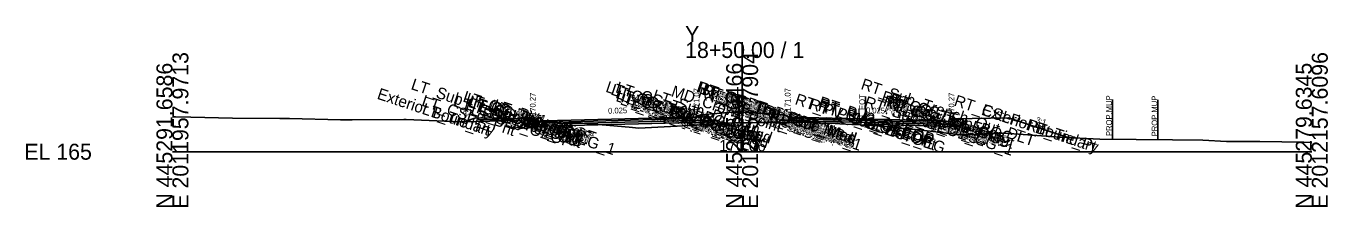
# Model space of a CAD drawing. Extents: x -26 to 3203, y -10 to 9532.
# Drawn here: x 974.3 to 1202.8, y 2490.3 to 2522.1 of the extents above; entities that cross this region are included whole.
import ezdxf

# ---------------------------------------------------------------- set-up
doc = ezdxf.new("R2010")
doc.units = 0
for name, color, linetype in [('Default', 7, 'Continuous'), ('Exist CMT Pavement', 7, 'Continuous'), ('Exist Cross Section Cell', 7, 'Continuous'), ('Exist XS Center Line Elevation Label', 7, 'Continuous'), ('Exist XS Ground Line', 7, 'Continuous'), ('Prop CMT Conc Surface', 7, 'Continuous'), ('Prop CMT Concrete Structures', 7, 'Continuous'), ('Prop CMT Pvmt Course 1', 7, 'Continuous'), ('Prop CMT Pvmt Course 1 CG', 7, 'Continuous'), ('Prop CMT Pvmt Course 2', 7, 'Continuous'), ('Prop CMT Pvmt Course 2 Wedge', 7, 'Continuous'), ('Prop CMT Pvmt Course 3', 7, 'Continuous'), ('Prop CMT Pvmt Course 3 Wedge', 7, 'Continuous'), ('Prop CMT Pvmt Surface', 7, 'Continuous'), ('Prop CMT Slope Grass', 7, 'Continuous'), ('Prop CMT Subgrade Earthwork', 7, 'Continuous'), ('Prop XS Hydro Elevations', 7, 'Continuous'), ('Prop XS Label Text', 7, 'Continuous'), ('Prop XS SE Text', 7, 'Continuous'), ('Prop XS Side Slope Text', 7, 'Continuous'), ('Scratch_Level_0', 7, 'Continuous')]:
    doc.layers.add(name, color=color, linetype=linetype)

msp = doc.modelspace()

# ---------------------------------------------------------------- linework, layer by layer
at = {"layer": 'Exist CMT Pavement'}
msp.add_lwpolyline([(1108.75, 2505.14), (1109.21, 2505.14), (1109.24, 2505.14), (1109.27, 2505.14), (1110.8, 2505.17), (1111.66, 2505.15), (1111.75, 2505.15), (1111.87, 2505.14), (1114.24, 2505.03), (1116.34, 2504.95), (1116.74, 2504.94), (1117.18, 2504.91), (1119.25, 2504.79), (1119.8, 2504.76), (1121.66, 2504.67), (1121.72, 2504.67), (1121.75, 2504.66), (1122.65, 2504.62), (1123.1, 2504.6), (1123.77, 2504.56)], dxfattribs=at)
at = {"layer": 'Exist Cross Section Cell'}
for p, q in [((1100, 2500), (1100, 2519.25)), ((1000, 2500), (1100, 2500)), ((1100, 2500), (1200, 2500))]:
    msp.add_line(p, q, dxfattribs=at)
at = {"layer": 'Exist XS Ground Line'}
msp.add_lwpolyline([(1000, 2506.15), (1000.53, 2506.15), (1003.22, 2506.08), (1010.55, 2505.87), (1018.83, 2505.82), (1020.57, 2505.8), (1029.49, 2505.6), (1030.59, 2505.61), (1031.57, 2505.59), (1040.61, 2505.63), (1041.02, 2505.63), (1047.77, 2505.37), (1050.81, 2505.25), (1060.65, 2505.45), (1061.47, 2505.43), (1070.67, 2505.13), (1080.19, 2504.28), (1081.89, 2504.12), (1088.55, 2504.51), (1098.48, 2505.04), (1098.93, 2505.05), (1099.5, 2505.06), (1100, 2505.06), (1101.09, 2505.06), (1101.74, 2505.07), (1103.9, 2505.1), (1104.25, 2505.11), (1104.56, 2505.11), (1106.76, 2505.12), (1109.27, 2505.14), (1110.8, 2505.17), (1111.87, 2505.14), (1114.24, 2505.03), (1116.34, 2504.95), (1116.74, 2504.94), (1117.18, 2504.91), (1119.25, 2504.79), (1119.8, 2504.76), (1121.66, 2504.67), (1122.65, 2504.62), (1123.1, 2504.6), (1123.77, 2504.56), (1131.01, 2503.86), (1138.47, 2502.96), (1146.09, 2503.28), (1155.86, 2502.55), (1162.82, 2502.2), (1175.55, 2502.11), (1180.88, 2502.03), (1185.01, 2501.82), (1190.9, 2501.78), (1198.59, 2501.65), (1200, 2501.64)], dxfattribs=at)
at = {"layer": 'Prop CMT Conc Surface'}
for points in [[(1058.75, 2505.86), (1053.75, 2505.96)], [(1063.25, 2505.27), (1063.25, 2505.77), (1062.75, 2505.77)], [(1065.25, 2505.4), (1063.25, 2505.27)], [(1091.25, 2506.05), (1092, 2506.07), (1092, 2506.24), (1092.76, 2506.49)], [(1108.75, 2506.05), (1108, 2506.07), (1108, 2506.24), (1107.24, 2506.49)], [(1134.75, 2505.4), (1136.75, 2505.27)], [(1136.75, 2505.27), (1136.75, 2505.77), (1137.25, 2505.77)]]:
    msp.add_lwpolyline(points, dxfattribs=at)
at = {"layer": 'Prop CMT Concrete Structures'}
for points in [[(1053.75, 2505.63), (1053.75, 2505.96)], [(1053.75, 2505.96), (1058.75, 2505.86)], [(1058.75, 2505.53), (1053.75, 2505.63)], [(1058.75, 2505.86), (1058.75, 2505.53)], [(1065.25, 2505.4), (1063.25, 2505.27), (1063.25, 2505.77), (1062.75, 2505.77)], [(1062.75, 2505.77), (1062.75, 2504.76), (1065.25, 2504.82)], [(1065.25, 2504.82), (1065.25, 2505.4)], [(1091.25, 2506.05), (1092, 2506.07), (1092, 2506.24), (1092.76, 2506.49)], [(1091.25, 2505.47), (1091.25, 2506.05)], [(1092.76, 2505.51), (1091.25, 2505.47)], [(1092.76, 2506.49), (1092.76, 2505.51)], [(1108.75, 2506.05), (1108, 2506.07), (1108, 2506.24), (1107.24, 2506.49)], [(1107.24, 2506.49), (1107.24, 2505.51)], [(1107.24, 2505.51), (1108.75, 2505.47)], [(1108.75, 2505.47), (1108.75, 2506.05)], [(1134.75, 2505.4), (1136.75, 2505.27), (1136.75, 2505.77), (1137.25, 2505.77)], [(1137.25, 2505.77), (1137.25, 2504.76), (1134.75, 2504.82)], [(1134.75, 2504.82), (1134.75, 2505.4)]]:
    msp.add_lwpolyline(points, dxfattribs=at)
at = {"layer": 'Prop CMT Pvmt Course 1'}
for points in [[(1091.25, 2506.05), (1065.25, 2505.4)], [(1065.25, 2505.15), (1091.25, 2505.8)], [(1065.25, 2505.4), (1065.25, 2505.15)], [(1091.25, 2505.8), (1091.25, 2506.05)], [(1091.25, 2505.8), (1091.25, 2505.8), (1091.25, 2505.8)], [(1108.75, 2506.05), (1134.75, 2505.4)], [(1108.75, 2505.8), (1108.75, 2506.05)], [(1134.75, 2505.15), (1123.77, 2505.43), (1108.75, 2505.8)], [(1108.75, 2505.8), (1108.75, 2505.8)], [(1134.75, 2505.4), (1134.75, 2505.15)]]:
    msp.add_lwpolyline(points, dxfattribs=at)
at = {"layer": 'Prop CMT Pvmt Course 1 CG'}
for points in [[(1065.25, 2504.82), (1062.25, 2504.74), (1061.91, 2504.4)], [(1065.25, 2504.49), (1065.25, 2504.82)], [(1091.25, 2505.47), (1093.26, 2505.52), (1093.59, 2505.19)], [(1091.25, 2505.14), (1091.25, 2505.47)], [(1093.59, 2505.19), (1091.25, 2505.14)], [(1108.75, 2505.47), (1106.74, 2505.52), (1106.41, 2505.19)], [(1106.41, 2505.19), (1108.75, 2505.14)], [(1108.75, 2505.14), (1108.75, 2505.47)], [(1134.75, 2504.82), (1137.75, 2504.74), (1138.09, 2504.4)], [(1134.75, 2504.49), (1134.75, 2504.82)], [(1061.91, 2504.4), (1065.25, 2504.49)], [(1138.09, 2504.4), (1134.75, 2504.49)]]:
    msp.add_lwpolyline(points, dxfattribs=at)
at = {"layer": 'Prop CMT Pvmt Course 2'}
for points in [[(1091.25, 2505.8), (1065.25, 2505.15)], [(1065.25, 2504.82), (1091.25, 2505.47)], [(1065.25, 2505.15), (1065.25, 2504.82)], [(1091.25, 2505.47), (1091.25, 2505.8)], [(1108.75, 2505.8), (1108.75, 2505.8)], [(1121.66, 2505.15), (1121.66, 2505.48)], [(1121.66, 2505.48), (1134.75, 2505.15)], [(1134.75, 2504.82), (1121.66, 2505.15)], [(1134.75, 2505.15), (1134.75, 2504.82)]]:
    msp.add_lwpolyline(points, dxfattribs=at)
msp.add_lwpolyline([(1108.75, 2505.8), (1108.75, 2505.47), (1108.75, 2505.47)], close=True, dxfattribs=at)
at = {"layer": 'Prop CMT Pvmt Course 2 Wedge'}
for points in [[(1108.75, 2505.47), (1108.75, 2505.8)], [(1108.75, 2505.8), (1109.21, 2505.79), (1109.24, 2505.79), (1109.27, 2505.79), (1110.8, 2505.75), (1111.66, 2505.73), (1111.75, 2505.73), (1111.87, 2505.72), (1114.24, 2505.66), (1116.34, 2505.61), (1116.74, 2505.6), (1117.18, 2505.59), (1119.25, 2505.54), (1119.8, 2505.53), (1121.66, 2505.48)], [(1121.66, 2505.15), (1119.8, 2505.19), (1119.25, 2505.21), (1117.18, 2505.26), (1116.74, 2505.27), (1116.34, 2505.28), (1114.24, 2505.33), (1111.87, 2505.39), (1111.75, 2505.39), (1111.66, 2505.4), (1110.8, 2505.42), (1109.27, 2505.46), (1109.24, 2505.46), (1109.21, 2505.46), (1108.75, 2505.47)], [(1121.66, 2505.48), (1121.66, 2505.15), (1121.66, 2505.15)]]:
    msp.add_lwpolyline(points, dxfattribs=at)
at = {"layer": 'Prop CMT Pvmt Course 3'}
for points in [[(1091.25, 2505.47), (1065.25, 2504.82)], [(1065.25, 2504.49), (1091.25, 2505.14)], [(1065.25, 2504.82), (1065.25, 2504.49)], [(1091.25, 2505.14), (1091.25, 2505.47)], [(1108.75, 2505.47), (1108.75, 2505.47), (1108.75, 2505.14), (1108.75, 2505.14)], [(1108.75, 2505.14), (1108.75, 2505.47)], [(1121.66, 2505.15), (1134.75, 2504.82)], [(1121.66, 2504.81), (1121.66, 2505.15)], [(1134.75, 2504.49), (1121.66, 2504.81)], [(1134.75, 2504.82), (1134.75, 2504.49)]]:
    msp.add_lwpolyline(points, dxfattribs=at)
at = {"layer": 'Prop CMT Pvmt Course 3 Wedge'}
for points in [[(1108.75, 2505.14), (1108.75, 2505.47)], [(1108.75, 2505.47), (1109.21, 2505.46), (1109.24, 2505.46), (1109.27, 2505.46), (1110.8, 2505.42), (1111.66, 2505.4), (1111.75, 2505.39), (1111.87, 2505.39), (1114.24, 2505.33), (1116.34, 2505.28), (1116.74, 2505.27), (1117.18, 2505.26), (1119.25, 2505.21), (1119.8, 2505.19), (1121.66, 2505.15)], [(1123.77, 2504.56), (1123.1, 2504.6), (1122.65, 2504.62), (1121.75, 2504.66), (1121.72, 2504.67), (1121.66, 2504.67), (1119.8, 2504.76), (1119.25, 2504.79), (1117.18, 2504.91), (1116.74, 2504.94), (1116.34, 2504.95), (1114.24, 2505.03), (1111.87, 2505.14), (1111.75, 2505.15), (1111.66, 2505.15), (1110.8, 2505.17), (1109.27, 2505.14), (1109.24, 2505.14), (1109.21, 2505.14), (1108.75, 2505.14)], [(1121.66, 2505.15), (1121.66, 2504.67)]]:
    msp.add_lwpolyline(points, dxfattribs=at)
at = {"layer": 'Prop CMT Pvmt Surface'}
for points in [[(1091.25, 2506.05), (1065.25, 2505.4)], [(1108.75, 2506.05), (1134.75, 2505.4)]]:
    msp.add_lwpolyline(points, dxfattribs=at)
at = {"layer": 'Prop CMT Slope Grass'}
for points in [[(1053.25, 2505.96), (1051.15, 2505.26)], [(1062.75, 2505.77), (1053.25, 2505.96)], [(1092.76, 2506.49), (1098.99, 2506.97)], [(1107.24, 2506.49), (1098.99, 2506.97)], [(1137.25, 2505.77), (1146.75, 2505.96)], [(1146.75, 2505.96), (1157.2, 2502.48)]]:
    msp.add_lwpolyline(points, dxfattribs=at)
at = {"layer": 'Prop CMT Subgrade Earthwork'}
for points in [[(1065.25, 2504.49), (1061.91, 2504.4), (1060.49, 2505.82)], [(1091.25, 2505.14), (1065.25, 2504.49)], [(1093.59, 2505.19), (1091.25, 2505.14)], [(1091.25, 2505.14), (1091.25, 2505.14)], [(1091.25, 2505.14), (1091.25, 2505.14)], [(1095.06, 2506.67), (1093.59, 2505.19)], [(1104.99, 2506.62), (1106.41, 2505.19)], [(1106.41, 2505.19), (1108.75, 2505.14)], [(1108.75, 2505.14), (1108.75, 2505.14)], [(1108.75, 2505.14), (1108.75, 2505.14)], [(1108.75, 2505.14), (1108.75, 2505.14)], [(1121.66, 2504.81), (1134.75, 2504.49)], [(1121.66, 2504.81), (1121.67, 2504.67)], [(1134.75, 2504.49), (1138.09, 2504.4), (1139.51, 2505.82)], [(1065.25, 2504.49), (1065.25, 2504.49)], [(1134.75, 2504.49), (1134.75, 2504.49)]]:
    msp.add_lwpolyline(points, dxfattribs=at)
at = {"layer": 'Prop XS Label Text'}
for p, q in [((1099.5, 2510.06), (1099.5, 2505.06)), ((1121.66, 2509.67), (1121.66, 2504.67)), ((1165, 2509.19), (1165, 2502.19)), ((1173, 2509.13), (1173, 2502.13))]:
    msp.add_line(p, q, dxfattribs=at)

# ---------------------------------------------------------------- texts
at = {"layer": 'Default'}
msp.add_text('-', height=0.0001, dxfattribs=at).set_placement((1000, 2500))
at = {"layer": 'Exist Cross Section Cell'}
for s, p in [('Y', (1090, 2519.25)), ('18+50.00 / 1', (1090, 2516.45)), ('EL 165', (974, 2498.6))]:
    msp.add_text(s, height=2.8, dxfattribs=at).set_placement(p)
for s, p in [('E 2011957.9713', (1002.8, 2490)), ('E 2012057.7904', (1102.8, 2490)), ('E 2012157.6096', (1202.8, 2490)), ('N 445291.6586', (1000, 2490)), ('N 445285.6466', (1100, 2490)), ('N 445279.6345', (1200, 2490))]:
    msp.add_text(s, height=2.8, rotation=90, dxfattribs=at).set_placement(p)
at = {"layer": 'Exist XS Center Line Elevation Label'}
msp.add_text('170.06', height=2, dxfattribs=at).set_placement((1095.97, 2500.06))
at = {"layer": 'Prop XS Hydro Elevations'}
for s, p in [('170.27', (1063.75, 2506.27)), ('171.07', (1092.5, 2507.07)), ('171.07', (1108.5, 2507.07)), ('170.27', (1137.25, 2506.27))]:
    msp.add_text(s, height=1, rotation=90, dxfattribs=at).set_placement(p)
at = {"layer": 'Prop XS Label Text'}
for s, p in [('E. EOT', (1099.4, 2506.08)), ('E. EOT', (1121.56, 2505.69)), ('PROP.MUP', (1164.9, 2502.76)), ('PROP.MUP', (1172.9, 2502.7))]:
    msp.add_text(s, height=1, rotation=90, dxfattribs=at).set_placement(p)
at = {"layer": 'Prop XS SE Text'}
for rotation, p in [(1.4321, (1076.49, 2506.68)), (358.5679, (1121.73, 2506.78))]:
    msp.add_text('0.025', height=1, rotation=rotation, dxfattribs=at).set_placement(p)
at = {"layer": 'Prop XS Side Slope Text'}
for rotation, p in [(18.4349, (1051.21, 2506.07)), (341.5651, (1151.47, 2505.18))]:
    msp.add_text('3:1', height=1, rotation=rotation, dxfattribs=at).set_placement(p)
at = {"layer": 'Scratch_Level_0'}
for s, p in [('LT_Sub_Trench_Out_DLT', (1041.74, 2511.01)), ('LT_CG_Top_Face_Med', (1075.91, 2510.55)), ('LT_CG_Top_Gut_Med', (1076.83, 2510.07)), ('LT_CG_Top_BOC_Med', (1077.64, 2510.47)), ('MD_Crown Point', (1087.42, 2509.77)), ('RT_CG_Top_Face_Med', (1091.86, 2510.56)), ('RT_CG_Top_BOC_Med', (1092.07, 2510.49)), ('RT_CG_Top_Gut_Med', (1092.79, 2510.09)), ('RT_Sub_Trench_Out_DLT', (1120.71, 2511.03)), ('Exterior Boundary', (1035.79, 2509.33)), ('LT_CSLP_Pnt', (1043.61, 2508.12)), ('LT_CG1_Shelf_Out', (1049.18, 2508.05)), ('LT_CG_Top_Face', (1050.85, 2508.85)), ('LT_CG_Top_BOC', (1051.32, 2508.53)), ('LT_CG_Bot_BOC', (1051.35, 2507.5)), ('LT_CG_Top_Gut', (1051.77, 2508.04)), ('LT_Sub_OEOT_CG_1', (1051.86, 2507.89)), ('LT_CG_Bot_BOC_Med', (1077.67, 2509.48)), ('LT_CG_Bot_IE_Med', (1077.71, 2508.93)), ('LT_Sub_IEOT_CG_1', (1078.47, 2508.34)), ('LT_Sub_OEEOP', (1080.7, 2507.6)), ('LT_PV2_OEEOP', (1080.79, 2508.23)), ('LT_PV3_OEEOP', (1080.79, 2507.9)), ('LT_PV2_IEEOP', (1081.4, 2508.03)), ('LT_CG1_Shelf_In', (1081.72, 2508.31)), ('LT_PV2_PGL', (1082.6, 2507.63)), ('LT_PV1_PGL', (1083.14, 2507.7)), ('LT_Sub_DLT_In', (1084.12, 2509.08)), ('RT_CG_Bot_BOC_Med', (1092.1, 2509.5)), ('RT_Sub_DLT_In', (1094.23, 2509.09)), ('RT_CG1_Shelf_In', (1095.16, 2508.33)), ('RT_CG_Bot_IE_Med', (1095.17, 2508.94)), ('RT_PV_Sub_Tie_In', (1095.63, 2508.45)), ('RT_Sub_IEOT_CG_1', (1095.93, 2508.35)), ('RT_PV_IEEOP_EG', (1097.18, 2507.94)), ('RT_PV2_IEEOP', (1098.86, 2508.05)), ('RT_PV3_IEEOP', (1098.86, 2507.71)), ('RT_PV2_PGL', (1100.05, 2507.65)), ('RT_PV1_PGL', (1100.59, 2507.72)), ('RT_PV_Sub_Tie_Out', (1109.14, 2508.38)), ('RT_PV_OEEOP_EG', (1111.59, 2507.56)), ('RT_PV2_OEEOP', (1113.27, 2507.87)), ('RT_PV3_OEEOP', (1113.27, 2507.54)), ('RT_Sub_OEOT_CG_1', (1121.32, 2507.91)), ('RT_CG_Top_Face', (1124.3, 2508.87)), ('RT_CG1_Shelf_Out', (1124.63, 2508.06)), ('RT_CG_Top_Gut', (1125.23, 2508.06)), ('RT_CG_Top_BOC', (1125.77, 2508.54)), ('RT_CG_Bot_BOC', (1125.8, 2507.52)), ('RT_CSLP_Pnt', (1137.07, 2508.14)), ('LT_Tie_Pt', (1043.66, 2506.7)), ('LT_Sub_OEOP', (1052.21, 2506.58)), ('LT_CG_Bot_IE', (1055.36, 2507.06)), ('LT_Sub_OEOT', (1055.52, 2506.67)), ('LT_PV2_OEOT', (1055.61, 2507.31)), ('LT_PV3_OEOT', (1055.61, 2506.98)), ('LT_PV1_OEOT', (1056.15, 2507.38)), ('LT_Sub_IEEOP', (1081.31, 2507.39)), ('LT_Sub_PGL', (1082.51, 2507)), ('LT_Sub_IEOP', (1084.5, 2507.17)), ('RT_Sub_IEOP', (1097.28, 2507.18)), ('RT_Sub_IEEOP', (1098.77, 2507.41)), ('RT_Sub_PGL', (1099.96, 2507.01)), ('RT_PV3_PGL', (1100.05, 2507.31)), ('RT_Sub_OEEOP', (1113.18, 2507.24)), ('RT_CG_Bot_IE', (1124.82, 2507.07)), ('RT_Sub_OEOT', (1124.98, 2506.69)), ('RT_PV2_OEOT', (1125.07, 2507.33)), ('RT_PV3_OEOT', (1125.07, 2506.99)), ('RT_PV1_OEOT', (1125.6, 2507.4)), ('RT_Sub_OEOP', (1128.35, 2506.6)), ('Exterior Boundary', (1141.86, 2506.54)), ('RT_Tie_Pt', (1149.69, 2503.93))]:
    msp.add_text(s, height=2, rotation=341.5651, dxfattribs=at).set_placement(p)

doc.saveas('drawing.dxf')
